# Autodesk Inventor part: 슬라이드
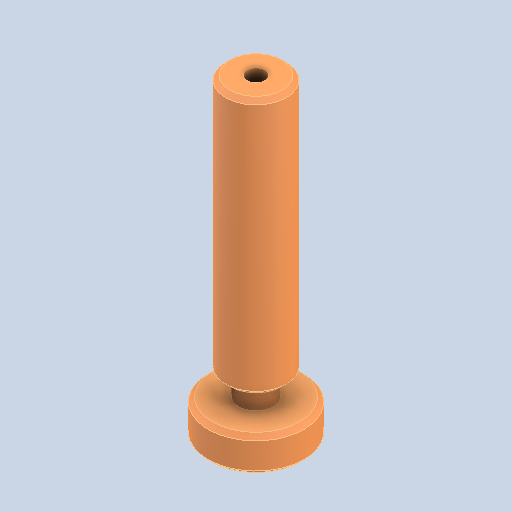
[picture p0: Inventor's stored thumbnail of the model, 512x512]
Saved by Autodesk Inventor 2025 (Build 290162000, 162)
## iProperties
Created: 2024-07
Part Number: 슬라이드
Material: 강철, 연강
Document SubType Name: Modeling
Designer: anfro
Density: 7.86 g/cm^3
Appearance: 기본값
Author: jhkim
Sending System: Autodesk Inventor 2025
Preprocessor: ST-DEVELOPER v20
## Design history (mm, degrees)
feature "솔리드1"
node "솔리드2"
